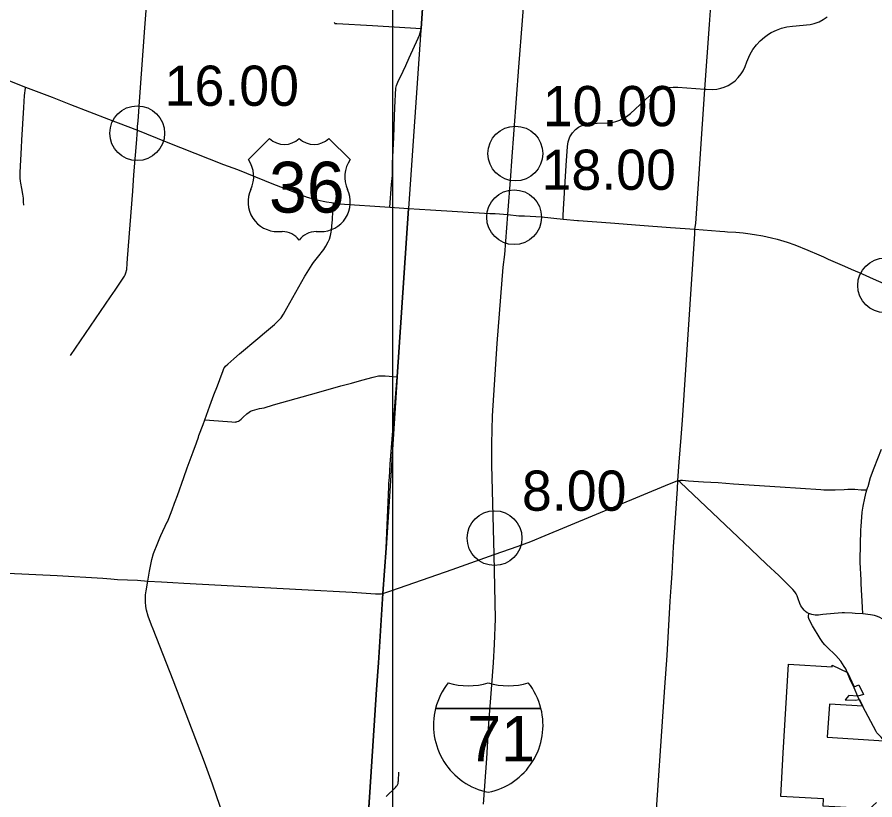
# Model space of a CAD drawing. Extents: x 1659811 to 1934326, y 644115 to 934867.
# Drawn here: x 1835797 to 1859282, y 809790 to 831231 of the extents above; entities that cross this region are included whole.
import ezdxf

# ---------------------------------------------------------------- set-up
doc = ezdxf.new("R2010")
doc.units = 0
for name, color, linetype in [('Default', 7, 'Continuous'), ('GM_X_City_Street', 7, 'Continuous'), ('GM_X_Corporation', 7, 'Continuous'), ('GM_X_County_Road', 7, 'Continuous'), ('GM_X_Interstate_Route', 7, 'Continuous'), ('GM_X_Interstate_Shield', 7, 'Continuous'), ('GM_X_Township', 7, 'Continuous'), ('GM_X_Township_Road', 7, 'Continuous'), ('GM_X_US_Route', 7, 'Continuous'), ('GM_X_US_Shield', 7, 'Continuous'), ('SH_Text', 7, 'Continuous')]:
    doc.layers.add(name, color=color, linetype=linetype)

msp = doc.modelspace()

# ---------------------------------------------------------------- linework, layer by layer
at = {"layer": 'Default'}
for centre in [(1839084, 828052), (1849439, 827494), (1849405, 825751), (1859563, 823882), (1848869, 816960)]:
    msp.add_circle(centre, 750, dxfattribs=at)
at = {"layer": 'GM_X_City_Street'}
msp.add_lwpolyline([(1858816, 812624), (1858712, 812860)], dxfattribs=at)
at = {"layer": 'GM_X_Corporation'}
msp.add_lwpolyline([(1859327, 809721), (1859138, 809540), (1857865, 809621), (1857876, 809816), (1856704, 809881), (1856773, 811076), (1856914, 813505), (1858114, 813436), (1858118, 813482), (1858535, 813283), (1858712, 812884), (1858845, 812940), (1858970, 812675), (1858813, 812629), (1858574, 812648), (1858471, 812534), (1858741, 812523), (1858864, 812540), (1858957, 812354), (1858043, 812416), (1857978, 811505), (1859535, 811404)], dxfattribs=at)
at = {"layer": 'GM_X_County_Road'}
for points in [[(1839090, 828131), (1839096, 828247), (1839106, 828377), (1839155, 829045), (1839297, 830940), (1839419, 832616), (1839427, 832761), (1839419, 832807), (1839405, 832831)], [(1846005, 826026), (1846043, 826645), (1846071, 826890), (1846074, 827230), (1846113, 827938), (1846126, 828505), (1846142, 828753), (1846166, 829288), (1846184, 829357), (1846219, 829446), (1846366, 829753), (1846439, 829908), (1846529, 830116), (1846779, 830659), (1846815, 830740), (1846834, 830797), (1846854, 830870), (1846863, 830918), (1846971, 832575)], [(1854753, 831025), (1854754, 831032), (1854771, 831285), (1854824, 832063), (1854821, 832136)], [(1854354, 825422), (1854377, 825574), (1854631, 829258), (1854753, 831025)], [(1850745, 825700), (1850750, 825794), (1850761, 825975), (1850834, 827165), (1850866, 827684), (1850884, 827817), (1850934, 827955), (1851000, 828061), (1851089, 828156), (1851167, 828213), (1851241, 828254), (1851342, 828291), (1851425, 828309), (1851528, 828316), (1851677, 828322), (1851998, 828336), (1852079, 828347), (1852187, 828372), (1852301, 828412), (1852366, 828442), (1852454, 828491), (1852522, 828537), (1852593, 828595), (1852985, 828961), (1853110, 829075), (1853198, 829141), (1853285, 829192), (1853384, 829239), (1853471, 829269), (1853550, 829290), (1853650, 829307), (1853759, 829315), (1853892, 829310), (1854631, 829258)], [(1837255, 821964), (1838352, 823573), (1838477, 823753), (1838734, 824138), (1838754, 824176), (1838776, 824230), (1838797, 824315), (1838813, 824478), (1838822, 824624), (1838961, 826468), (1838996, 826913), (1839038, 827452), (1839065, 827768), (1839090, 828131)], [(1844428, 825666), (1844430, 825701), (1844439, 825894), (1844455, 826141)], [(1843676, 824135), (1843691, 824163), (1843825, 824382), (1843877, 824459), (1843910, 824506), (1843948, 824557), (1844017, 824645), (1844192, 824870), (1844248, 824955), (1844313, 825075), (1844345, 825149), (1844376, 825251), (1844395, 825340), (1844404, 825395), (1844424, 825605), (1844428, 825666)], [(1853892, 818538), (1853927, 819045), (1853979, 819713), (1854011, 820193), (1854357, 825298), (1854354, 825422)], [(1840108, 817915), (1840125, 817960), (1840185, 818129), (1840360, 818619), (1840456, 818888), (1840615, 819321), (1840707, 819568), (1840763, 819722), (1840773, 819774), (1840889, 820072), (1840934, 820196), (1841077, 820583), (1841186, 820882), (1841282, 821134), (1841343, 821301), (1841435, 821553), (1841459, 821602), (1841482, 821642), (1841498, 821666), (1841562, 821727), (1841728, 821872), (1841885, 822009), (1842387, 822426), (1842567, 822583), (1842842, 822816), (1842945, 822908), (1843026, 822996), (1843091, 823097), (1843134, 823175), (1843183, 823260), (1843512, 823845), (1843676, 824135)], [(1853892, 818538), (1853963, 818545), (1854011, 818543), (1854178, 818529), (1854595, 818503), (1854991, 818481), (1855415, 818448), (1856692, 818365), (1857805, 818293), (1857887, 818287), (1857997, 818281), (1858195, 818286), (1858439, 818296), (1858547, 818299), (1858647, 818302), (1858736, 818299), (1858909, 818286), (1858969, 818282), (1859024, 818279), (1859060, 818281), (1859080, 818337), (1859095, 818374), (1859163, 818625), (1859262, 818885), (1859464, 819395)], [(1845813, 815443), (1846057, 815523), (1847704, 816100), (1848860, 816509), (1849512, 816739), (1849867, 816870), (1850255, 817032), (1853548, 818404), (1853845, 818524), (1853892, 818538)], [(1852972, 804706), (1852981, 804856), (1853110, 806745), (1853175, 807697), (1853246, 808714), (1853530, 812876), (1853592, 813742), (1853681, 815234), (1853705, 815613), (1853731, 815995), (1853772, 816725), (1853832, 817646), (1853875, 818312), (1853892, 818538)], [(1857182, 815299), (1857153, 815378), (1857124, 815436), (1857089, 815491), (1857039, 815553), (1856865, 815727), (1856650, 815933), (1856316, 816250), (1855886, 816655), (1854135, 818318), (1853948, 818496), (1853892, 818538)], [(1839372, 815780), (1839425, 816059), (1839488, 816370), (1839533, 816537), (1839646, 816828), (1839707, 816968), (1839735, 817030), (1839908, 817404), (1839909, 817406), (1839949, 817498), (1840041, 817739), (1840108, 817915)], [(1831958, 816015), (1832323, 815989), (1832460, 815979), (1832837, 815953), (1832930, 815950), (1833024, 815953), (1833112, 815962), (1833413, 816008), (1833762, 816064), (1833870, 816076), (1833979, 816082), (1834125, 816080), (1834617, 816051), (1834676, 816048), (1834735, 816046), (1835535, 816000), (1836888, 815933), (1838141, 815859), (1838366, 815848), (1838544, 815828), (1839093, 815806), (1839372, 815780)], [(1842846, 805301), (1842837, 805328), (1842772, 805518), (1842519, 806229), (1841146, 810217), (1840928, 810827), (1840065, 813066), (1839518, 814468), (1839479, 814577), (1839387, 814825), (1839342, 814985), (1839324, 815084), (1839310, 815214), (1839307, 815315), (1839311, 815371), (1839312, 815408), (1839319, 815463), (1839325, 815513), (1839372, 815780)], [(1839372, 815780), (1839750, 815761), (1840057, 815746), (1840358, 815730), (1843594, 815549), (1844974, 815476), (1845607, 815434), (1845771, 815433), (1845813, 815443)], [(1858745, 814899), (1858660, 814905), (1858449, 814910), (1858391, 814909), (1858164, 814898), (1857861, 814864), (1857798, 814856), (1857739, 814849), (1857648, 814850), (1857559, 814865), (1857530, 814873), (1857479, 814893), (1857433, 814917), (1857388, 814948), (1857347, 814984), (1857307, 815028), (1857257, 815108), (1857229, 815169), (1857182, 815299)], [(1861324, 812212), (1861236, 812378), (1860992, 812846), (1860828, 813174), (1860617, 813548), (1860476, 813746), (1860173, 814063), (1859848, 814400), (1859708, 814543), (1859640, 814615), (1859568, 814682), (1859482, 814748), (1859421, 814784), (1859356, 814815), (1859277, 814840), (1859165, 814861), (1858949, 814884), (1858745, 814899)]]:
    msp.add_lwpolyline(points, dxfattribs=at)
at = {"layer": 'GM_X_Interstate_Route'}
for points in [[(1849232, 825823), (1849312, 826884), (1849342, 827283), (1849536, 829857), (1849737, 832422), (1849949, 835289), (1849960, 835440)], [(1848565, 809674), (1848656, 810925), (1848716, 811884), (1848786, 812818), (1848839, 813548), (1848865, 814059), (1848894, 814749), (1848860, 816509), (1848794, 818972), (1848791, 819542), (1848815, 820309), (1848943, 822290), (1849103, 824378), (1849147, 824725), (1849232, 825823)]]:
    msp.add_lwpolyline(points, dxfattribs=at)
at = {"layer": 'GM_X_Interstate_Shield'}
for p, q in [((1847254, 812294), (1850140, 812294)), ((1850140, 812294), (1847254, 812294)), ((1850140, 812294), (1847254, 812294)), ((1847254, 812294), (1850140, 812294)), ((1850140, 812294), (1847254, 812294)), ((1850140, 812294), (1847254, 812294))]:
    msp.add_line(p, q, dxfattribs=at)
for centre, start, end in [((1849072, 811835), 141.669, 165.8066), ((1849072, 811835), 141.669, 165.8066), ((1848149, 814791), 253.0091, 286.9909), ((1848149, 814791), 253.0091, 286.9909), ((1849245, 814791), 253.0091, 286.9909), ((1849245, 814791), 253.0091, 286.9909), ((1848322, 811835), 14.1934, 38.331), ((1848322, 811835), 14.1934, 38.331), ((1849072, 811835), 165.8066, 258.463), ((1849072, 811835), 165.8066, 258.463), ((1848322, 811835), 281.537, 14.1934), ((1848322, 811835), 281.537, 14.1934)]:
    msp.add_arc(centre, 1875, start, end, dxfattribs=at)
at = {"layer": 'GM_X_Township'}
msp.add_lwpolyline([(1846971, 832575), (1846863, 830918), (1846854, 830870), (1846509, 825988), (1846205, 821378), (1845900, 816686), (1845813, 815443), (1845687, 813540), (1845670, 813309), (1845637, 812811), (1845452, 810003), (1845333, 808188), (1845296, 807619), (1845145, 805182), (1843287, 805303), (1843103, 805315), (1843041, 805313), (1842837, 805328), (1840812, 805456), (1837716, 805633), (1832763, 805986)], dxfattribs=at)
at = {"layer": 'GM_X_Township_Road'}
for points in [[(1854631, 829258), (1854661, 829256), (1854846, 829249), (1854959, 829261), (1855061, 829283), (1855161, 829315), (1855264, 829362), (1855369, 829424), (1855456, 829490), (1855539, 829573), (1855621, 829675), (1855677, 829764), (1855733, 829882), (1855778, 830005), (1855828, 830130), (1855872, 830221), (1855943, 830341), (1856042, 830473), (1856145, 830584), (1856260, 830683), (1856373, 830763), (1856446, 830807), (1856586, 830875), (1856728, 830927), (1856876, 830964), (1857032, 830986), (1857514, 831030), (1857625, 831055), (1857756, 831102), (1857871, 831163), (1857978, 831239)], [(1844480, 831093), (1844497, 831060), (1844550, 831060), (1845524, 831004), (1846863, 830918)], [(1835977, 826077), (1835975, 826171), (1835970, 826275), (1835952, 826385), (1835926, 826541), (1835897, 826684), (1835886, 826742), (1835877, 826818), (1835875, 826895), (1835879, 826972), (1835915, 827662), (1835926, 827862), (1835981, 828758), (1836002, 829086), (1836021, 829286), (1836024, 829315)], [(1846205, 821378), (1846509, 825988)], [(1840934, 820196), (1841554, 820152), (1841675, 820144), (1841771, 820139), (1841789, 820141), (1841806, 820145), (1841824, 820150), (1841857, 820165), (1841886, 820186), (1841932, 820222), (1841987, 820273), (1842088, 820362), (1842150, 820411), (1842188, 820437), (1842243, 820457), (1842436, 820506), (1842558, 820533), (1842815, 820608), (1843441, 820786), (1843996, 820944), (1844660, 821131), (1844951, 821209), (1845239, 821285), (1845542, 821368), (1845693, 821404), (1845774, 821406), (1845873, 821404), (1846205, 821378)], [(1845813, 815443), (1845900, 816686), (1845973, 818365), (1845978, 818443), (1845984, 818548), (1845988, 818619), (1846010, 818988), (1846205, 821378)], [(1858949, 814884), (1858944, 815073), (1858908, 815711), (1858905, 815815), (1858883, 816289), (1858879, 816365), (1858902, 817190), (1858907, 817282), (1858933, 817671), (1858963, 817835), (1859010, 818058), (1859043, 818222), (1859060, 818281)], [(1845336, 808240), (1845452, 810003), (1845637, 812811), (1845670, 813309), (1845687, 813540), (1845813, 815443)], [(1858524, 813285), (1858523, 813288), (1858486, 813376), (1858444, 813445), (1858400, 813513), (1858350, 813585), (1858214, 813747), (1857968, 813983), (1857911, 814041), (1857857, 814102), (1857782, 814210), (1857579, 814557), (1857484, 814732), (1857467, 814783), (1857464, 814822), (1857479, 814893)], [(1858712, 812860), (1858703, 812880), (1858602, 813109), (1858524, 813285)], [(1858858, 812530), (1858854, 812539), (1858816, 812624)], [(1858951, 812345), (1858946, 812355), (1858888, 812469), (1858858, 812530)], [(1859516, 811426), (1859452, 811506), (1859339, 811630), (1859319, 811662), (1858951, 812345)], [(1845901, 809883), (1846157, 810131), (1846187, 810162), (1846202, 810185), (1846214, 810206), (1846226, 810238), (1846229, 810261), (1846233, 810284), (1846236, 810308), (1846248, 810548)]]:
    msp.add_lwpolyline(points, dxfattribs=at)
at = {"layer": 'GM_X_US_Route'}
for points in [[(1833463, 830322), (1836024, 829315), (1836751, 829041), (1837258, 828837), (1838300, 828432), (1839090, 828131), (1839877, 827816), (1841448, 827196), (1841834, 827061), (1842819, 826655), (1843343, 826451), (1843520, 826379), (1843742, 826300), (1843999, 826225), (1844265, 826170), (1844402, 826149)], [(1844402, 826149), (1844455, 826141), (1844585, 826124), (1844623, 826121), (1846005, 826026), (1846509, 825988)], [(1846509, 825988), (1847116, 825949), (1848742, 825856), (1848890, 825849), (1849232, 825823)], [(1849232, 825823), (1849538, 825792), (1849689, 825784)], [(1849689, 825784), (1850151, 825758), (1850745, 825700), (1851142, 825661), (1851169, 825659)], [(1851169, 825659), (1852041, 825594), (1852847, 825534), (1853684, 825470), (1854354, 825422), (1855037, 825370)], [(1855037, 825370), (1855173, 825360), (1855248, 825354), (1855476, 825337), (1855674, 825320), (1855808, 825306), (1855988, 825281), (1856219, 825240), (1856454, 825186), (1856610, 825146), (1856879, 825067), (1857093, 824992), (1857448, 824848), (1857746, 824717), (1857872, 824661)], [(1857872, 824661), (1858002, 824603), (1858452, 824407), (1858634, 824327), (1858849, 824233), (1859315, 824029), (1859681, 823869), (1859988, 823723), (1860406, 823477), (1860588, 823365), (1860963, 823124), (1861157, 822990), (1861474, 822783), (1861713, 822608), (1861927, 822435), (1862088, 822291), (1862329, 822071), (1862359, 822043)]]:
    msp.add_lwpolyline(points, dxfattribs=at)
at = {"layer": 'GM_X_US_Shield'}
for p, q in [((1842708, 827907), (1842128, 827327)), ((1842708, 827907), (1842128, 827327)), ((1844912, 827327), (1844332, 827907)), ((1844912, 827327), (1844332, 827907)), ((1842940, 825355), (1843056, 825355)), ((1842940, 825355), (1843056, 825355)), ((1843984, 825355), (1844100, 825355)), ((1843984, 825355), (1844100, 825355))]:
    msp.add_line(p, q, dxfattribs=at)
for centre, radius, start, end in [((1843114, 828322), 580, 225.573, 314.427), ((1843114, 828322), 580, 225.573, 314.427), ((1843926, 828322), 580, 225.573, 314.427), ((1843926, 828322), 580, 225.573, 314.427), ((1841463, 826861), 812, 334.5471, 35.0009), ((1841463, 826861), 812, 334.5471, 35.0009), ((1845578, 826861), 812, 144.9991, 205.4529), ((1845578, 826861), 812, 144.9991, 205.4529), ((1842931, 826167), 812, 154.8319, 270.6383), ((1842931, 826167), 812, 154.8319, 270.6383), ((1844109, 826167), 812, 269.3617, 25.1681), ((1844109, 826167), 812, 269.3617, 25.1681), ((1843056, 824775), 580, 36.8699, 90), ((1843056, 824775), 580, 36.8699, 90), ((1843984, 824775), 580, 90, 143.1301), ((1843984, 824775), 580, 90, 143.1301)]:
    msp.add_arc(centre, radius, start, end, dxfattribs=at)
at = {"layer": 'SH_Text'}
msp.add_lwpolyline([(1741462, 842026), (1846073, 842026), (1846073, 754070), (1741462, 754070)], close=True, dxfattribs=at)

# ---------------------------------------------------------------- texts
at = {"layer": 'Default'}
for s, p in [('16.00', (1839834, 828802)), ('10.00', (1850189, 828244)), ('18.00', (1850155, 826501)), ('8.00', (1849619, 817710))]:
    msp.add_text(s, height=1100, dxfattribs=at).set_placement(p)
at = {"layer": 'GM_X_Interstate_Shield'}
msp.add_text('71', height=1250, dxfattribs=at).set_placement((1848119, 810841))
msp.add_text('71', height=1250, dxfattribs=at).set_placement((1848119, 810841))
at = {"layer": 'GM_X_US_Shield'}
msp.add_text('36', height=1392.2, dxfattribs=at).set_placement((1842693, 825877))
msp.add_text('36', height=1392.2, dxfattribs=at).set_placement((1842693, 825877))

doc.saveas('drawing.dxf')
